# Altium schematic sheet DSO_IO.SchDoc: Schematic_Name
size A4; CompanyName: University of Melbourne; Engineer: Your Name Here; DocumentNumber: 1; Revision: 0.1; SheetNumber: 1; SheetTotal: 1; Title_Project: Project_Title; StudentNo: Student No.
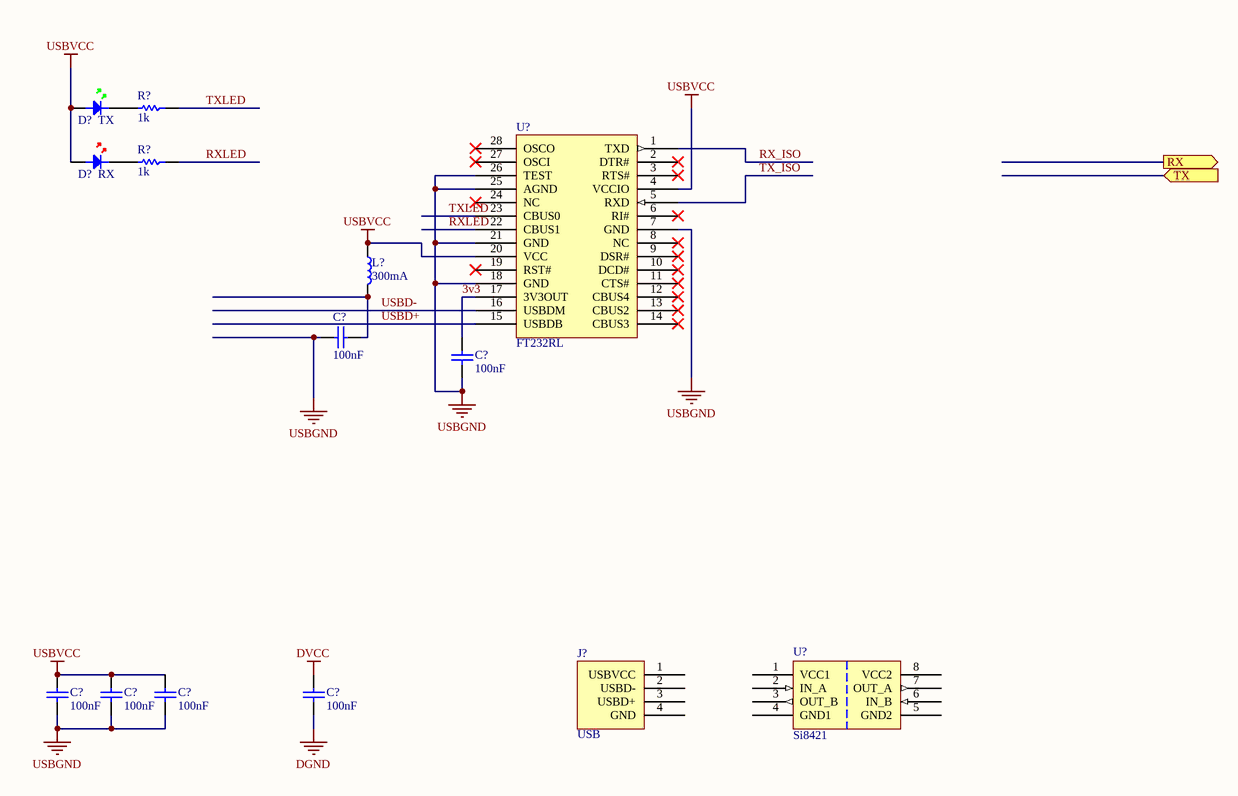
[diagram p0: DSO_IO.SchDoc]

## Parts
(Parts that share a designator on the sheet are numbered #1, #2 ... from top to bottom, then left to right.)
C?#1  100nF  [0805C]
C?#2  100nF  [0805C]
C?#3  100nF  [0805C]
C?#4  100nF  [0805C]
C?#5  100nF  [0805C]
C?#6  100nF  [0805C]
D?#1  TX  [0805D-GREEN]
D?#2  RX  [0805D-RED]
J?  USB  [USBPLUG]
L?  300mA  [0805]
R?#1  1k  [0805]
R?#2  1k  [0805]
U?#1  FT232RL  [SSOP-28]
U?#2  Si8421  [SOIC-8]

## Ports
RX (out), TX (in)

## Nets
DGND: C?#6.2
DVCC: C?#6.1
USBGND: C?#1.2 C?#2.2 C?#3.2 C?#4.2 C?#5.2 U?#1.7(GND) U?#1.18(GND) U?#1.21(GND) U?#1.25(AGND) U?#1.26(TEST)
USBVCC: C?#3.1 C?#4.1 C?#5.1 D?#1.A D?#2.A L?.1 U?#1.4(VCCIO) U?#1.20(VCC)
3v3: C?#2.1 U?#1.17(3V3OUT)
RX_ISO: U?#1.1(TXD)
RXLED: R?#2.1 U?#1.22(CBUS1)
TX_ISO: U?#1.5(RXD)
TXLED: R?#1.1 U?#1.23(CBUS0)
USBD+: U?#1.15(USBDB)
USBD-: U?#1.16(USBDM)
NetC?#1_1: C?#1.1 L?.2
NetD?#1_K: D?#1.K R?#1.2
NetD?#2_K: D?#2.K R?#2.2

Not connected (* = marked no-connect by the designer): J? 1(USBVCC) 2(USBD-) 3(USBD+) 4(GND); U?#1 2(DTR#)* 3(RTS#)* 6(RI#)* 8(NC)* 9(DSR#)* 10(DCD#)* 11(CTS#)* 12(CBUS4)* 13(CBUS2)* 14(CBUS3)* 19(RST#)* 24(NC)* 27(OSCI)* 28(OSCO)*; U?#2 1(VCC1) 2(IN_A) 3(OUT_B) 4(GND1) 5(GND2) 6(IN_B) 7(OUT_A) 8(VCC2)

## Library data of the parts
C?#1-C?#6 = C: Capacitor; Reviewed by: RM - 2018/08/05
D?#1 = LED GREEN: Light Emitting Diode; Reviewed by: RM - 2018/08/05
D?#2 = LED RED: Light Emitting Diode; Reviewed by: RM - 2018/08/05
J? = USBPLUG: USB B Type Connector; Reviewed by: RM - 2018/08/05
L? = I: Inductor; Reviewed by: RM - 2018/08/05
R?#1 R?#2 = R: Resistor; Reviewed by: RM - 2018/08/05
U?#1 = FT232RL: USB to Serial bridge; Reviewed by: RM - 2018/08/05
U?#2 = Si8421: Dual Channel Digital Isolator Both Ways; Reviewed by: RM - 2018/08/05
